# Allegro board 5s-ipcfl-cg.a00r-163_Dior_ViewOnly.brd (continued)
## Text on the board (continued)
Ref Des/Silkscreen Top: S1 | S2 | L2 | L1 | SW10 | P12 | U6 | PPID1 | H13 | J218 | Y5 | E16 | 5 | 3 | 1 | JMP1 | U9435 | 4 | 6 | 2 | U9434 | PU3 | Y18 | H14 | E61 | P305 | PU5 | SC53 | J303 | XU1 | 3,4 | 5,6 | 1,2 | SERVICE_MODE | PASSWORD_CLR | CMOS_CLR | FUNCTION | SHORT:DISABLE | OPEN:DEFAULT | SHORT:CLEAR | OPEN:CLEAR | SHORT:DEFAULT | OPERATION | PCE9 | C178 | CR15 | SSD_Q1 | JP2802 | LINE OUT | JP2801 | HEATSINK | J68 | PCE97027 | PCE97031 | PCE97028 | PCE97037 | PCE97035 | PCE97038 | AMB_Q1 | PCE97034 | PCE97033 | USB4 | HD# LED | AUDIO JACK | U1 | J219 | J8 | CLIP1 | J301 | P110 | ROM RECOVERY | J89 | J13 | USB3 | J200 | USB1 | J12 | USB2 | J133 | INTRUDER | DIMM2 | DP | J302 | HDMI | J125 | REV:A00 | DIMM1 | J1 | POWER BTN | PCB MADE IN CHINA | SSD Thermal PAD | LAN | XBT1 | SS USB2 | CLIP2 | SS USB1 | DC IN | P6 | P70 | D33D66 | 180 degree | 0 degree | R
GND: list("[Spacing] GND" "16.Shape to Route Keepin" "0 MIL [DEFAULT]" "0 MIL" "0.00 MIL" "DRC ERROR CLASS/GND" "[Shape] Route Keepin/All ((-3483.94 -2629.6) (3168.97 4113.86))" "[Gnd Shape] GND_AUDIO ((-3205.0 -2629.6) (-1679.0 -1669.72))" list(-2574.810000 -2401.260000) nil)@@@list("eric2_tseng" "2019/01/23 17:32:05" nil "p143000044-pc" "5s-ipcfl-cg.a00r")@@@list("doris_chen" "2019/01/24 12:51:16" nil "p16c000356-pc" "5s-ipcfl-cg.a00r-chk") | list("[Physical] GND" "202.Pad/Pad Direct Connect" "NOT_ALLOWED [DEFAULT]" "ALL_ALLOWED" "" "DRC ERROR CLASS/GND" "[ThruPin] PCH_HEATSINK_DET (<uTiL>cId6011<uTiL>.4) (-2152.51 -10.63)" "[ThruPin] PCH_HEATSINK_DET (<uTiL>cId5725<uTiL>.1) (-2152.52 -10.63)" list(-2152.520000 -10.630000) nil)@@@list("eric2_tseng" "2019/01/23 17:34:32" nil "p143000044-pc" "5s-ipcfl-cg.a00r")@@@list("doris_chen" "2019/01/24 12:53:07" nil "p16c000356-pc" "5s-ipcfl-cg.a00r-chk") | list("[Physical] GND" "201.Pad/Pad Direct Connect" "NOT_ALLOWED [DEFAULT]" "ALL_ALLOWED" "" "DRC ERROR CLASS/GND" "[ThruPin] PCH_HEATSINK_DET (<uTiL>cId5725<uTiL>.2) (-2152.52 189.37)" "[ThruPin] PCH_HEATSINK_DET (<uTiL>cId6011<uTiL>.3) (-2152.51 189.37)" list(-2152.510000 189.370000) nil)@@@list("eric2_tseng" "2019/01/23 17:34:32" nil "p143000044-pc" "5s-ipcfl-cg.a00r")@@@list("doris_chen" "2019/01/24 12:53:07" nil "p16c000356-pc" "5s-ipcfl-cg.a00r-chk") | list("[Spacing] GND" "19.Thru Pin to Thru Pin" "5 MIL [DEFAULT]" "OVERLAP" "" "DRC ERROR CLASS/GND" "[ThruPin] Dummy (<uTiL>cId3746<uTiL>.2) (-359.85 883.07)" "[ThruPin] Dummy (<uTiL>cId3746<uTiL>.1) (-359.85 932.28)" list(-359.850000 847.780000) nil)@@@list("eric2_tseng" "2019/01/23 17:32:05" nil "p143000044-pc" "5s-ipcfl-cg.a00r")@@@list("doris_chen" "2019/01/24 12:51:17" nil "p16c000356-pc" "5s-ipcfl-cg.a00r-chk") | list("[Spacing] GND" "18.Thru Pin to Thru Pin" "5 MIL [DEFAULT]" "OVERLAP" "" "DRC ERROR CLASS/GND" "[ThruPin] Dummy (<uTiL>cId864<uTiL>.1) (-334.64 -788.19)" "[ThruPin] Dummy (<uTiL>cId864<uTiL>.2) (-334.64 -868.11)" list(-334.640000 -866.690000) nil)@@@list("eric2_tseng" "2019/01/23 17:32:06" nil "p143000044-pc" "5s-ipcfl-cg.a00r")@@@list("doris_chen" "2019/01/24 12:51:17" nil "p16c000356-pc" "5s-ipcfl-cg.a00r-chk") | list("[Spacing] GND" "17.Shape to Route Keepin" "0 MIL [DEFAULT]" "0 MIL" "0.00 MIL" "DRC ERROR CLASS/GND" "[Shape] Route Keepin/All ((-3483.94 -2629.6) (3168.97 4113.86))" "[Gnd Shape] GND ((-3483.94 -2629.6) (3168.97 4113.86))" list(1843.980000 -2381.570000) nil)@@@list("eric2_tseng" "2019/01/23 17:32:04" nil "p143000044-pc" "5s-ipcfl-cg.a00r")@@@list("doris_chen" "2019/01/24 12:51:16" nil "p16c000356-pc" "5s-ipcfl-cg.a00r-chk")
IN1: list("[Physical] IN1" "204.Pad/Pad Direct Connect" "NOT_ALLOWED [DEFAULT]" "ALL_ALLOWED" "" "DRC ERROR CLASS/IN1" "[ThruPin] PCH_HEATSINK_DET (<uTiL>cId6011<uTiL>.4) (-2152.51 -10.63)" "[ThruPin] PCH_HEATSINK_DET (<uTiL>cId5725<uTiL>.1) (-2152.52 -10.63)" list(-2152.520000 -10.630000) nil)@@@list("eric2_tseng" "2019/01/23 17:34:35" nil "p143000044-pc" "5s-ipcfl-cg.a00r")@@@list("doris_chen" "2019/01/24 12:53:08" nil "p16c000356-pc" "5s-ipcfl-cg.a00r-chk") | list("[Physical] IN1" "203.Pad/Pad Direct Connect" "NOT_ALLOWED [DEFAULT]" "ALL_ALLOWED" "" "DRC ERROR CLASS/IN1" "[ThruPin] PCH_HEATSINK_DET (<uTiL>cId5725<uTiL>.2) (-2152.52 189.37)" "[ThruPin] PCH_HEATSINK_DET (<uTiL>cId6011<uTiL>.3) (-2152.51 189.37)" list(-2152.510000 189.370000) nil)@@@list("eric2_tseng" "2019/01/23 17:34:34" nil "p143000044-pc" "5s-ipcfl-cg.a00r")@@@list("doris_chen" "2019/01/24 12:53:08" nil "p16c000356-pc" "5s-ipcfl-cg.a00r-chk") | list("[Spacing] IN1" "20.Shape to Route Keepin" "0 MIL [DEFAULT]" "0 MIL" "0.00 MIL" "DRC ERROR CLASS/IN1" "[Shape] Route Keepin/All ((-3483.94 -2629.6) (3168.97 4113.86))" "[In1 Shape] GND ((-1658.98 -2629.61) (-814.86 -2440.41))" list(-972.440000 -2629.600000) nil)@@@list("eric2_tseng" "2019/01/23 17:32:08" nil "p143000044-pc" "5s-ipcfl-cg.a00r")@@@list("doris_chen" "2019/01/24 12:51:18" nil "p16c000356-pc" "5s-ipcfl-cg.a00r-chk") | list("[Spacing-SameNet] IN1" "40.Thru Pin to Thru Pin Same Net" "5 MIL [DEFAULT]" "OVERLAP" "" "DRC ERROR CLASS/IN1" "[ThruPin] GND (<uTiL>cId5726<uTiL>.2) (-794.25 1990.95)" "[ThruPin] GND (<uTiL>cId6011<uTiL>.1) (-794.25 1990.95)" list(-763.250000 1990.950000) nil)@@@list("eric2_tseng" "2019/01/23 17:32:58" nil "p143000044-pc" "5s-ipcfl-cg.a00r")@@@list("doris_chen" "2019/01/24 12:51:34" nil "p16c000356-pc" "5s-ipcfl-cg.a00r-chk") | list("[Spacing-SameNet] IN1" "39.Thru Pin to Thru Pin Same Net" "5 MIL [DEFAULT]" "OVERLAP" "" "DRC ERROR CLASS/IN1" "[ThruPin] GND (<uTiL>cId5726<uTiL>.1) (-794.25 1790.95)" "[ThruPin] GND (<uTiL>cId6011<uTiL>.2) (-794.25 1790.95)" list(-763.250000 1790.950000) nil)@@@list("eric2_tseng" "2019/01/23 17:32:57" nil "p143000044-pc" "5s-ipcfl-cg.a00r")@@@list("doris_chen" "2019/01/24 12:51:33" nil "p16c000356-pc" "5s-ipcfl-cg.a00r-chk") | list("[Spacing] IN1" "22.Drill Hole to Drill Hole" "8 MIL [DEFAULT]" "OVERLAP" "" "DRC ERROR CLASS/IN1" "[ThruPin] Dummy (<uTiL>cId3746<uTiL>.2) (-359.85 883.07)" "[ThruPin] Dummy (<uTiL>cId3746<uTiL>.1) (-359.85 932.28)" list(-359.850000 847.780000) nil)@@@list("eric2_tseng" "2019/01/23 17:32:09" nil "p143000044-pc" "5s-ipcfl-cg.a00r")@@@list("doris_chen" "2019/01/24 12:51:19" nil "p16c000356-pc" "5s-ipcfl-cg.a00r-chk") | list("[Spacing] IN1" "21.Drill Hole to Drill Hole" "8 MIL [DEFAULT]" "OVERLAP" "" "DRC ERROR CLASS/IN1" "[ThruPin] Dummy (<uTiL>cId864<uTiL>.1) (-334.64 -788.19)" "[ThruPin] Dummy (<uTiL>cId864<uTiL>.2) (-334.64 -868.11)" list(-334.640000 -866.690000) nil)@@@list("eric2_tseng" "2019/01/23 17:32:09" nil "p143000044-pc" "5s-ipcfl-cg.a00r")@@@list("doris_chen" "2019/01/24 12:51:18" nil "p16c000356-pc" "5s-ipcfl-cg.a00r-chk")
IN2: list("[Spacing] IN2" "4.Shape to Route Keepout" "0 MIL [DEFAULT]" "0 MIL" "0.00 MIL" "DRC ERROR CLASS/IN2" "[Shape] Route Keepout/All ((-3363.8 -570.56) (-3302.8 -509.56))" "[In2 Shape] +5VSB ((-3456.02 -1344.99) (-2455.0 1132.0))" list(-3359.570000 -555.550000) nil)@@@list("eric2_tseng" "2019/01/23 17:32:13" nil "p143000044-pc" "5s-ipcfl-cg.a00r")@@@nil | list("[Physical] IN2" "206.Pad/Pad Direct Connect" "NOT_ALLOWED [DEFAULT]" "ALL_ALLOWED" "" "DRC ERROR CLASS/IN2" "[ThruPin] PCH_HEATSINK_DET (<uTiL>cId6011<uTiL>.4) (-2152.51 -10.63)" "[ThruPin] PCH_HEATSINK_DET (<uTiL>cId5725<uTiL>.1) (-2152.52 -10.63)" list(-2152.520000 -10.630000) nil)@@@list("eric2_tseng" "2019/01/23 17:34:38" nil "p143000044-pc" "5s-ipcfl-cg.a00r")@@@list("doris_chen" "2019/01/24 12:53:09" nil "p16c000356-pc" "5s-ipcfl-cg.a00r-chk") | list("[Physical] IN2" "205.Pad/Pad Direct Connect" "NOT_ALLOWED [DEFAULT]" "ALL_ALLOWED" "" "DRC ERROR CLASS/IN2" "[ThruPin] PCH_HEATSINK_DET (<uTiL>cId5725<uTiL>.2) (-2152.52 189.37)" "[ThruPin] PCH_HEATSINK_DET (<uTiL>cId6011<uTiL>.3) (-2152.51 189.37)" list(-2152.510000 189.370000) nil)@@@list("eric2_tseng" "2019/01/23 17:34:37" nil "p143000044-pc" "5s-ipcfl-cg.a00r")@@@list("doris_chen" "2019/01/24 12:53:09" nil "p16c000356-pc" "5s-ipcfl-cg.a00r-chk") | list("[Spacing] IN2" "24.Shape to Route Keepin" "0 MIL [DEFAULT]" "0 MIL" "0.00 MIL" "DRC ERROR CLASS/IN2" "[Shape] Route Keepin/All ((-3483.94 -2629.6) (3168.97 4113.86))" "[In2 Shape] GND ((-1658.98 -2629.61) (-814.86 -2440.41))" list(-972.440000 -2629.600000) nil)@@@list("eric2_tseng" "2019/01/23 17:32:11" nil "p143000044-pc" "5s-ipcfl-cg.a00r")@@@list("doris_chen" "2019/01/24 12:51:20" nil "p16c000356-pc" "5s-ipcfl-cg.a00r-chk") | list("[Spacing-SameNet] IN2" "42.Thru Pin to Thru Pin Same Net" "5 MIL [DEFAULT]" "OVERLAP" "" "DRC ERROR CLASS/IN2" "[ThruPin] GND (<uTiL>cId5726<uTiL>.2) (-794.25 1990.95)" "[ThruPin] GND (<uTiL>cId6011<uTiL>.1) (-794.25 1990.95)" list(-763.250000 1990.950000) nil)@@@list("eric2_tseng" "2019/01/23 17:33:03" nil "p143000044-pc" "5s-ipcfl-cg.a00r")@@@list("doris_chen" "2019/01/24 12:51:35" nil "p16c000356-pc" "5s-ipcfl-cg.a00r-chk") | list("[Spacing-SameNet] IN2" "41.Thru Pin to Thru Pin Same Net" "5 MIL [DEFAULT]" "OVERLAP" "" "DRC ERROR CLASS/IN2" "[ThruPin] GND (<uTiL>cId5726<uTiL>.1) (-794.25 1790.95)" "[ThruPin] GND (<uTiL>cId6011<uTiL>.2) (-794.25 1790.95)" list(-763.250000 1790.950000) nil)@@@list("eric2_tseng" "2019/01/23 17:33:02" nil "p143000044-pc" "5s-ipcfl-cg.a00r")@@@list("doris_chen" "2019/01/24 12:51:34" nil "p16c000356-pc" "5s-ipcfl-cg.a00r-chk") | list("[Spacing] IN2" "3.Shape to Route Keepout" "0 MIL [DEFAULT]" "0 MIL" "0.00 MIL" "DRC ERROR CLASS/IN2" "[Shape] Route Keepout/All ((-681.48 1420.2) (-620.48 1481.2))" "[In2 Shape] +VCCSA ((-997.48 1312.0) (878.11 2127.49))" list(-620.480000 1450.700000) nil)@@@list("eric2_tseng" "2019/01/23 17:32:12" nil "p143000044-pc" "5s-ipcfl-cg.a00r")@@@nil | list("[Spacing] IN2" "25.Drill Hole to Drill Hole" "8 MIL [DEFAULT]" "OVERLAP" "" "DRC ERROR CLASS/IN2" "[ThruPin] Dummy (<uTiL>cId3746<uTiL>.2) (-359.85 883.07)" "[ThruPin] Dummy (<uTiL>cId3746<uTiL>.1) (-359.85 932.28)" list(-359.850000 847.780000) nil)@@@list("eric2_tseng" "2019/01/23 17:32:12" nil "p143000044-pc" "5s-ipcfl-cg.a00r")@@@list("doris_chen" "2019/01/24 12:51:20" nil "p16c000356-pc" "5s-ipcfl-cg.a00r-chk") | list("[Spacing] IN2" "23.Drill Hole to Drill Hole" "8 MIL [DEFAULT]" "OVERLAP" "" "DRC ERROR CLASS/IN2" "[ThruPin] Dummy (<uTiL>cId864<uTiL>.1) (-334.64 -788.19)" "[ThruPin] Dummy (<uTiL>cId864<uTiL>.2) (-334.64 -868.11)" list(-334.640000 -866.690000) nil)@@@list("eric2_tseng" "2019/01/23 17:32:15" nil "p143000044-pc" "5s-ipcfl-cg.a00r")@@@list("doris_chen" "2019/01/24 12:51:19" nil "p16c000356-pc" "5s-ipcfl-cg.a00r-chk")
VCC: list("[Spacing] VCC" "30.Shape to Route Keepin" "0 MIL [DEFAULT]" "0 MIL" "0.00 MIL" "DRC ERROR CLASS/VCC" "[Shape] Route Keepin/All ((-3483.94 -2629.6) (3168.97 4113.86))" "[Vcc Shape] GND_AUDIO ((-3205.0 -2629.6) (-1679.0 -1669.72))" list(-2574.810000 -2401.260000) nil)@@@list("eric2_tseng" "2019/01/23 17:32:42" nil "p143000044-pc" "5s-ipcfl-cg.a00r")@@@list("doris_chen" "2019/01/24 12:51:29" nil "p16c000356-pc" "5s-ipcfl-cg.a00r-chk") | list("[Physical] VCC" "208.Pad/Pad Direct Connect" "NOT_ALLOWED [DEFAULT]" "ALL_ALLOWED" "" "DRC ERROR CLASS/VCC" "[ThruPin] PCH_HEATSINK_DET (<uTiL>cId6011<uTiL>.4) (-2152.51 -10.63)" "[ThruPin] PCH_HEATSINK_DET (<uTiL>cId5725<uTiL>.1) (-2152.52 -10.63)" list(-2152.520000 -10.630000) nil)@@@list("eric2_tseng" "2019/01/23 17:34:41" nil "p143000044-pc" "5s-ipcfl-cg.a00r")@@@list("doris_chen" "2019/01/24 12:53:10" nil "p16c000356-pc" "5s-ipcfl-cg.a00r-chk") | list("[Physical] VCC" "207.Pad/Pad Direct Connect" "NOT_ALLOWED [DEFAULT]" "ALL_ALLOWED" "" "DRC ERROR CLASS/VCC" "[ThruPin] PCH_HEATSINK_DET (<uTiL>cId5725<uTiL>.2) (-2152.52 189.37)" "[ThruPin] PCH_HEATSINK_DET (<uTiL>cId6011<uTiL>.3) (-2152.51 189.37)" list(-2152.510000 189.370000) nil)@@@list("eric2_tseng" "2019/01/23 17:34:40" nil "p143000044-pc" "5s-ipcfl-cg.a00r")@@@list("doris_chen" "2019/01/24 12:53:10" nil "p16c000356-pc" "5s-ipcfl-cg.a00r-chk") | list("[Spacing] VCC" "31.Thru Pin to Thru Pin" "5 MIL [DEFAULT]" "OVERLAP" "" "DRC ERROR CLASS/VCC" "[ThruPin] Dummy (<uTiL>cId3746<uTiL>.2) (-359.85 883.07)" "[ThruPin] Dummy (<uTiL>cId3746<uTiL>.1) (-359.85 932.28)" list(-359.850000 847.780000) nil)@@@list("eric2_tseng" "2019/01/23 17:32:43" nil "p143000044-pc" "5s-ipcfl-cg.a00r")@@@list("doris_chen" "2019/01/24 12:51:29" nil "p16c000356-pc" "5s-ipcfl-cg.a00r-chk") | list("[Spacing] VCC" "29.Thru Pin to Thru Pin" "5 MIL [DEFAULT]" "OVERLAP" "" "DRC ERROR CLASS/VCC" "[ThruPin] Dummy (<uTiL>cId864<uTiL>.1) (-334.64 -788.19)" "[ThruPin] Dummy (<uTiL>cId864<uTiL>.2) (-334.64 -868.11)" list(-334.640000 -866.690000) nil)@@@list("eric2_tseng" "2019/01/23 17:32:44" nil "p143000044-pc" "5s-ipcfl-cg.a00r")@@@list("doris_chen" "2019/01/24 12:51:28" nil "p16c000356-pc" "5s-ipcfl-cg.a00r-chk") | list("[Spacing] VCC" "28.Shape to Thru Via" "6 MIL [(5)]" "0 MIL" "6.00 MIL" "DRC ERROR CLASS/VCC" "[ThruVia] SLP_LAN# (VIA20D10A30) (113.0 -1642.0)" "[Vcc Shape] +5VSB ((-1794.0 -2015.0) (107.0 -1170.0))" list(107.000000 -1634.000000) nil)@@@list("eric2_tseng" "2019/01/23 17:32:43" nil "p143000044-pc" "5s-ipcfl-cg.a00r")@@@list("doris_chen" "2019/01/24 12:51:28" nil "p16c000356-pc" "5s-ipcfl-cg.a00r-chk") | list("[Spacing] VCC" "26.Shape to Thru Via" "6 MIL [DEFAULT]" "0 MIL" "6.00 MIL" "DRC ERROR CLASS/VCC" "[ThruVia] SLP_LAN# (VIA20D10A30) (113.0 -1642.0)" "[Vcc Shape] GND ((-3483.94 -2629.6) (3168.97 4113.86))" list(117.000000 -1632.830000) nil)@@@list("eric2_tseng" "2019/01/23 17:32:41" nil "p143000044-pc" "5s-ipcfl-cg.a00r")@@@list("doris_chen" "2019/01/24 12:51:21" nil "p16c000356-pc" "5s-ipcfl-cg.a00r-chk") | list("[Spacing] VCC" "27.Shape to Route Keepin" "0 MIL [DEFAULT]" "0 MIL" "0.00 MIL" "DRC ERROR CLASS/VCC" "[Shape] Route Keepin/All ((-3483.94 -2629.6) (3168.97 4113.86))" "[Vcc Shape] GND ((-3483.94 -2629.6) (3168.97 4113.86))" list(2036.110000 -2318.340000) nil)@@@list("eric2_tseng" "2019/01/23 17:32:42" nil "p143000044-pc" "5s-ipcfl-cg.a00r")@@@list("doris_chen" "2019/01/24 12:51:27" nil "p16c000356-pc" "5s-ipcfl-cg.a00r-chk")
LOGO: ECO NUMBER | D9-MICRO3:976992
User.27: R | 12 | 24 | S1 | P1 | 260 | 259 | 2 | 1 | 36 | S2 | L2 | L1 | SW10 | H7 | U6 | b | H4 | PPID1 | H13 | J218 | Y5 | E16 | 4 | 6 | U9435 | H2 | 5 | 9 | 13 | 3 | H14 | PU3 | Y18 | E61 | U9434 | P305 | PU5 | 17 | SC53 | J303 | 10 | XU1 | JMP1 | 3,4 | 5,6 | 1,2 | SERVICE_MODE | PASSWORD_CLR | CMOS_CLR | FUNCTION | SHORT:DISABLE | OPEN:DEFAULT | SHORT:CLEAR | OPEN:CLEAR | SHORT:DEFAULT | OPERATION | PCE9 | AMB_Q1 | C178 | SSD_Q2 | SSD_Q1 | JP2802 | LINE_OUT | JP2801 | PCH_HEATSINK | J68 | PCE97027 | PCE97031 | PCE97028 | PCE97037 | PCE97035 | PCE97038 | PCE97034 | PCE97033 | PEGATRON PROPRIETARY AND CONFIDENTIAL | TEL:(02)81439001 FAX:(02)28973868 | TAIPEI | www.pegatroncorp.com | DESIGNED BY PEGATRON CORPORATION | F2 | U1 | ECO NUMBER | D8-MICRO7-65:866645 | DESIGNER: | DATE: | LAY#: | 2017.07.27/14:01:25 | 5S-IPCFL-CG.X00 | AMY_CHOU | P12 | ROM_RECOVERY | SSD | J219 | J8 | CLIP1 | J301 | HD#_LED | M.2 | P110 | J89 | J13 | USB3 | J200 | VIDEO | USB1 | J12 | USB2 | J133 | INTRUDER | DP | DIMM2 | A | J302 | HDMI | J125 | REV:X00 | DIMM1 | J1 | POWER_BTN | PCB MADE IN CHINA | LAN | XBT1 | AUDIO_JACK | USB4 | SS_USB2 | CLIP2 | SS_USB1 | DC_IN | P6 | P70 | R&D DEPARTMENT/ENGINEER: | PROJECT DESCRIPTION: | MODEL NAME: | IPCFL-CG | BU5/Roger Lien | MAIN BOARD | REV. | X00 | SILKSCREEN | PRIMARY-SIDE | D33D66 | 180 degree | 0 degree
User.28: 6 | 1 | 16 | 11 | 64 | 96 | U104 | 8 | U114 | 24 | U23 | U7201 | 32 | 39 | PU89001 | 13 | 26 | PU4 | PU9 | PEGATRON PROPRIETARY AND CONFIDENTIAL | TEL:(02)81439001 FAX:(02)28973868 | TAIPEI | www.pegatroncorp.com | DESIGNED BY PEGATRON CORPORATION | ECO NUMBER | D8-MICRO7-65:866645 | DESIGNER: | DATE: | LAY#: | 2017.07.27/14:01:25 | 5S-IPCFL-CG.X00 | AMY_CHOU | XDP3 | P466 | XDP1 | R&D DEPARTMENT/ENGINEER: | PROJECT DESCRIPTION: | MODEL NAME: | IPCFL-CG | BU5/Roger Lien | MAIN BOARD | REV. | X00 | SILKSCREEN | SECONDARY-SIDE
